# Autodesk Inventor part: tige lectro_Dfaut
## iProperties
Created: 2007-07
Part Number: tige lectro_Dfaut
Document SubType Name: Modeling
Designer: EF
Density: 1 g/cm^3
Author: EF
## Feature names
1. Base1
